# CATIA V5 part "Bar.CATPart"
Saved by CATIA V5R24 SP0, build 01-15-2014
Part number: Bar
Bounding box of the stored display mesh (mm): x -5 to 70, y -5 to 5, z -5 to 5
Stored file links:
  \\cdl-main\FTPSERVER\Minsik\2016\2\Bar.CATPart
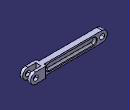
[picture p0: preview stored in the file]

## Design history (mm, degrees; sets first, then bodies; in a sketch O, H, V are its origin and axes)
Set1
  Sketch1 on zx-plane, origin (0, 0, 0), H (-1, 0, 0), V (0, 0, 1)
    line L1 (-65, 5) -> (0, 5)
    point P2 (0, 5)
    arc A1 centre (0, 0) radius 5 from (0, 5) to (0, -5) cw
    line L2 (0, -5) -> (-65, -5)
    arc A2 centre (-65, 0) radius 5 from (-65, -5) to (-65, 5) cw
    point P6 (-65, 0)
    radius A1 = 5
    distance P6 V = 65
    coincidence: P2 V
    horizontal: L1 H
    tangency: A1 L1, L2 A1, A2 L1, A2 L2
    symmetry: L1 L2 H
Body1 (main body)
  Pad1: profile Sketch1, direction (0, 1, 0), length 5
  Sketch2 on start face of Pad1, origin (0, 0, 0), H (1, 0, 0), V (0, 0, 1)
    line L1 (57.5, 9.5649) -> (57.5, -9.1746)
    distance L1 V = 57.5
    vertical: L1 V
  Pocket1: profile Sketch2, direction (0, 1, 0), length 2.5
  Sketch3 on end face of Pad1, origin (0, 5, 0), H (-1, 0, 0), V (0, 0, 1)
    line L1 (-54.5, 10.8692) -> (-54.5, -9.3221)
    distance L1 V = 54.5
    vertical: L1 V
  Pocket2: profile Sketch3, direction (0, -1, 0), length 2.5
  Fillet1: radius 1.5, on edge [end face of Pad1 | face of Pocket2 from Sketch3.L1]
  Sketch4 on end face of Pad1, origin (67.694, 5, 0.541), H (1, 0, 0), V (0, 0, -1)
    point P1 (-2.694, 0.541)
    reference projected arc E1 centre (-2.694, 0.541) radius 5 from (-2.694, -4.459) to (-2.694, 5.541) ccw from edge [face of Pad1 from Sketch1.A2 | end face of Pad1]
    concentricity: E1 P1
  Hole1: placed by Sketch4, at (65, 5, 0) direction (0, -1, 0), diameter 5, through (limit type 6)
  Sketch5 on end face of Pocket2, origin (1.6474, 2.5, -2.754), H (1, 0, 0), V (0, 0, -1)
    point P1 (-1.6474, -2.754)
    reference projected arc E1 centre (-1.6474, -2.754) radius 5 from (-1.6474, 2.246) to (-1.6474, -7.754) ccw from edge [end face of Pocket2 | face of Pad1 from Sketch1.A1]
    concentricity: E1 P1
  Hole2: placed by Sketch5, at (0, 2.5, 0) direction (0, -1, 0), diameter 5, through (limit type 6)
  Sketch6 on end face of Pocket2, origin (0, 2.5, 0), H (-1, 0, 0), V (0, 0, 1)
    construction line L1 (-8, 0) -> (-50, 0)
    point P1 (-8, 0)
    point P2 (-50, 0)
    line L2 (-8, -3) -> (-50, -3)
    line L3 (-50, 3) -> (-8, 3)
    arc A1 centre (-50, 0) radius 3 from (-50, -3) to (-50, 3) cw
    arc A2 centre (-8, 0) radius 3 from (-8, 3) to (-8, -3) cw
    distance L1 L2 = 3
    distance P1 V = 8
    distance P1 P2 = 42
    coincidence: P1 H
    horizontal: L1 H
    tangency: A1 L2, A2 L2, A1 L3, A2 L3
  Pocket3: profile Sketch6, direction (0, -1, 0), length 2
  Fillet2: radius 1.5, on edge [face of Pocket3 from Sketch6.A2 | end face of Pocket3]
  Fillet3: radius 0.5, on edge [end face of Pocket2 | face of Pocket3 from Sketch6.A2]
  Mirror1: of the body so far, about zx-plane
